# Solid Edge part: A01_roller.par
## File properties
Author: mokuno
Template: jis part.par
Last saved by: edge
Revision: 6
Application: Solid Edge
文書内容のタイプ: 0
Accuracy: 0.990
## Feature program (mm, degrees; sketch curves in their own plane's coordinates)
sketch for "unnamed Protrusion 1" plane through (0, 0, 0) normal (1, 0, 0) x-axis (0, 1, 0)
  circle centre (0, 0) radius 14
extrude "unnamed Protrusion 1" add finite 180 symmetric
sketch for "ExtrudedProtrusion_2" plane through (0, 0, 0) normal (1, 0, 0) x-axis (0, 1, 0)
  circle centre (0, 0) radius 18
extrude "ExtrudedProtrusion_2" add finite 140 symmetric
sketch for "ExtrudedProtrusion_3" plane through (0, 0, 0) normal (1, 0, 0) x-axis (0, 1, 0)
  circle centre (0, 0) radius 30
extrude "ExtrudedProtrusion_3" add finite 120 symmetric
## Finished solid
Body 1: solid body, 11 faces, 10 edges, 0 vertices.
  Faces by surface: plane 6, cylinder 5
  Edges by curve: circle 10
Bounding box of the edges (mm): 180.000 x 60.000 x 60.000, from (-90, -30, -30) to (90, 30, 30).
Cylindrical faces by radius (mm): R14 x2, R18 x2, R30 x1
Planar faces by outward normal: +x 3, -x 3
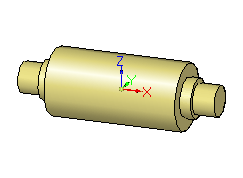
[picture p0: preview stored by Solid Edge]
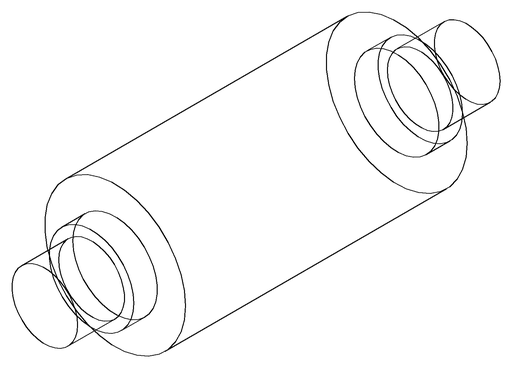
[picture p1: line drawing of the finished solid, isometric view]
